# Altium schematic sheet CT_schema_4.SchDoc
size 293 x 258 mm
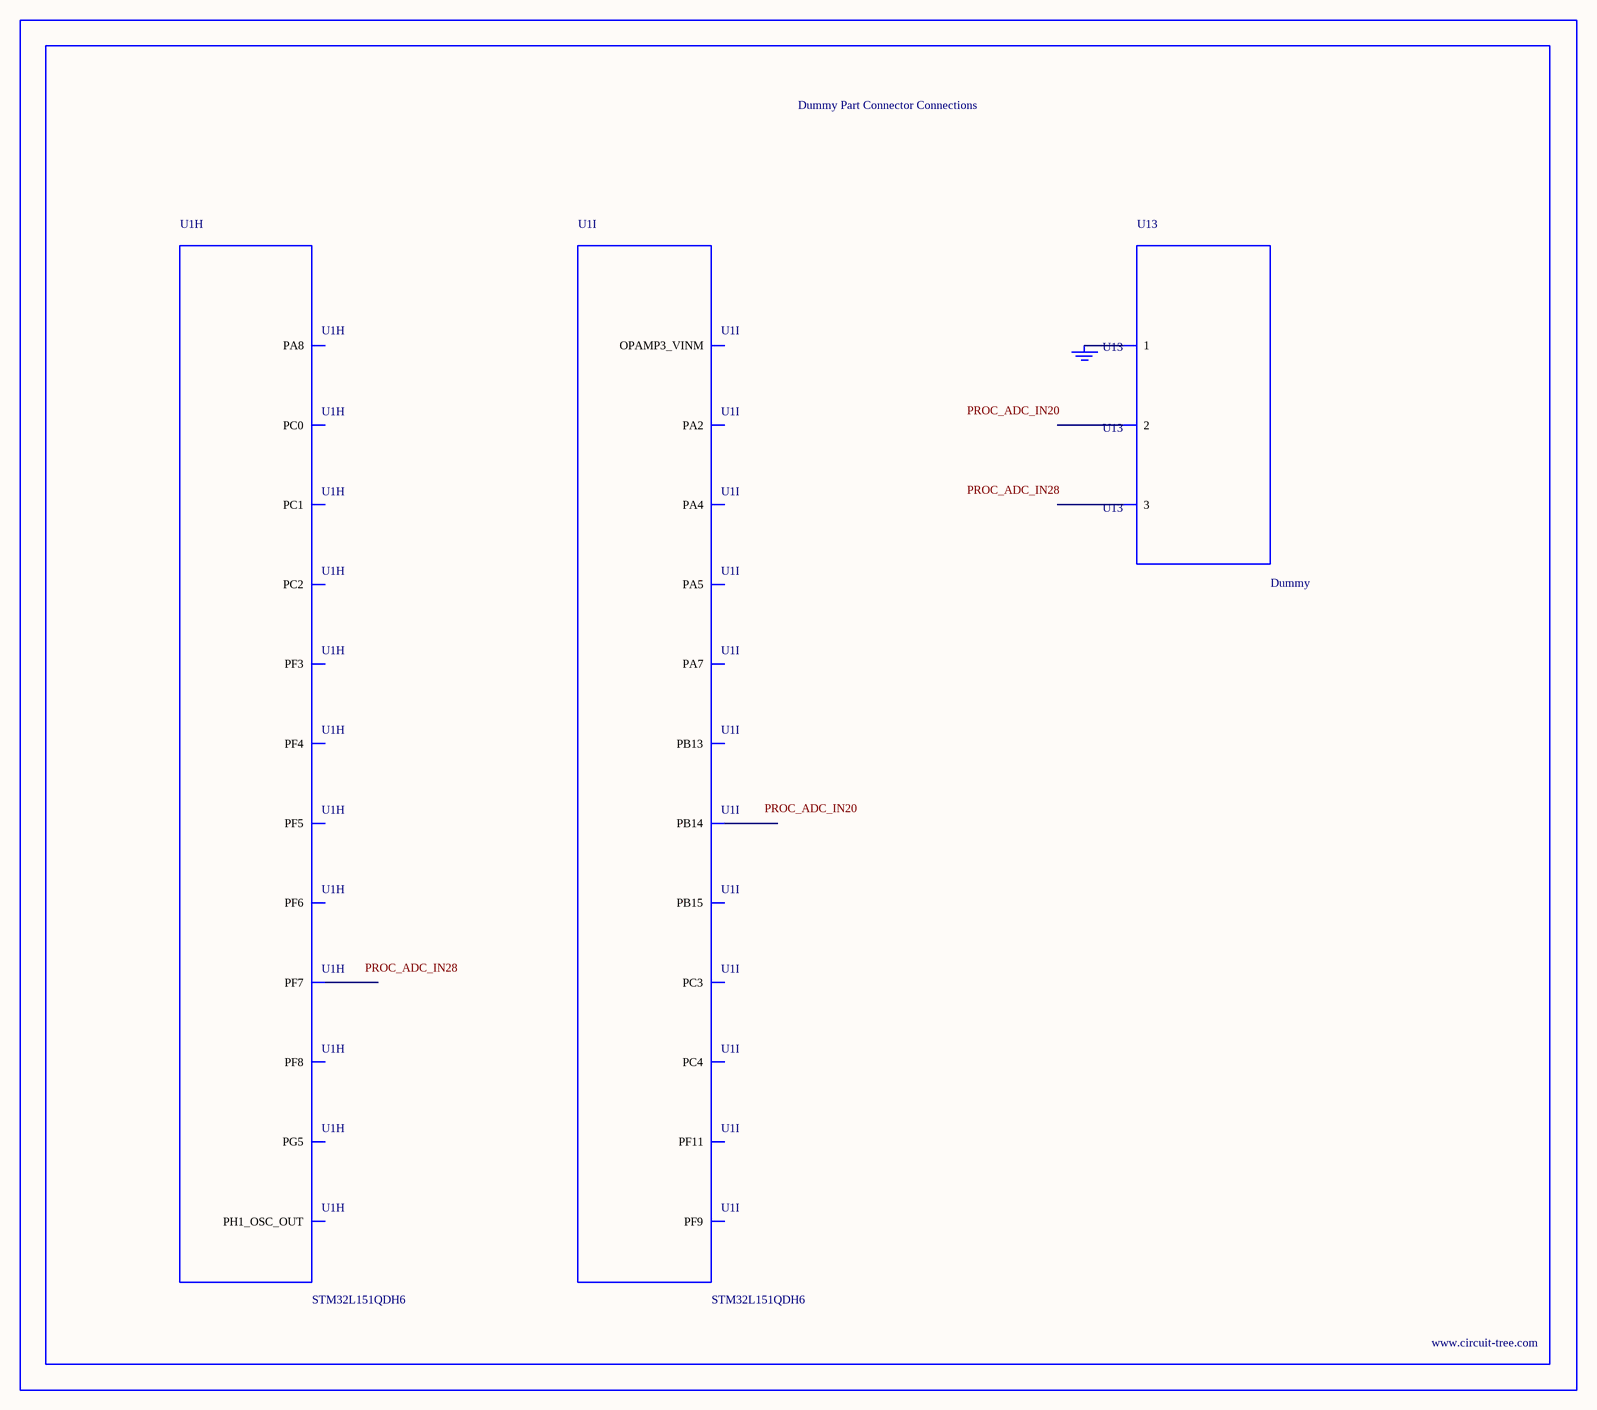
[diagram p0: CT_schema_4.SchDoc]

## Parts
BORDER3  (no value)
GND_INSTANCE_3_0  (no value)
U1  STM32L151QDH6  [UFBGA132]  (parts H,I of 9)
U13  Dummy  [DUMMY_PACKAGE_176]

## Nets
NetGND_INSTANCE_3_0_0: GND_INSTANCE_3_0.0(GND) U13.1

Not connected (* = marked no-connect by the designer): U1 D11(PA8) E4(PF3) E9(PG5) F3(PF4) F4(PF5) G1(PH1_OSC_OUT) G3(PF6) G4(PF7) H1(PC0) H4(PF8) J2(PC1) J3(PC2) J4(PA4) J5(PA7) J6(PF9) K1(OPAMP3_VINM) K2(PC3) K3(PA2) K4(PA5) K5(PC4) K6(PF11) K10(PB15) K11(PB14) K12(PB13); U13 2 3

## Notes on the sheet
- Labels drawn without touching a wire or pin: PROC_ADC_IN20, PROC_ADC_IN28

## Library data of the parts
BORDER3 = BORDER_PAGE3
GND_INSTANCE_3_0 = GND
